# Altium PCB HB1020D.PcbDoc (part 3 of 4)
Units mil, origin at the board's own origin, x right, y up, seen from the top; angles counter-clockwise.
Board outline 4729.44 x 3075.9 mil, 2 copper layers (Top Layer, Bottom Layer); 113 components, 129 nets, 454 pads, 503 vias.
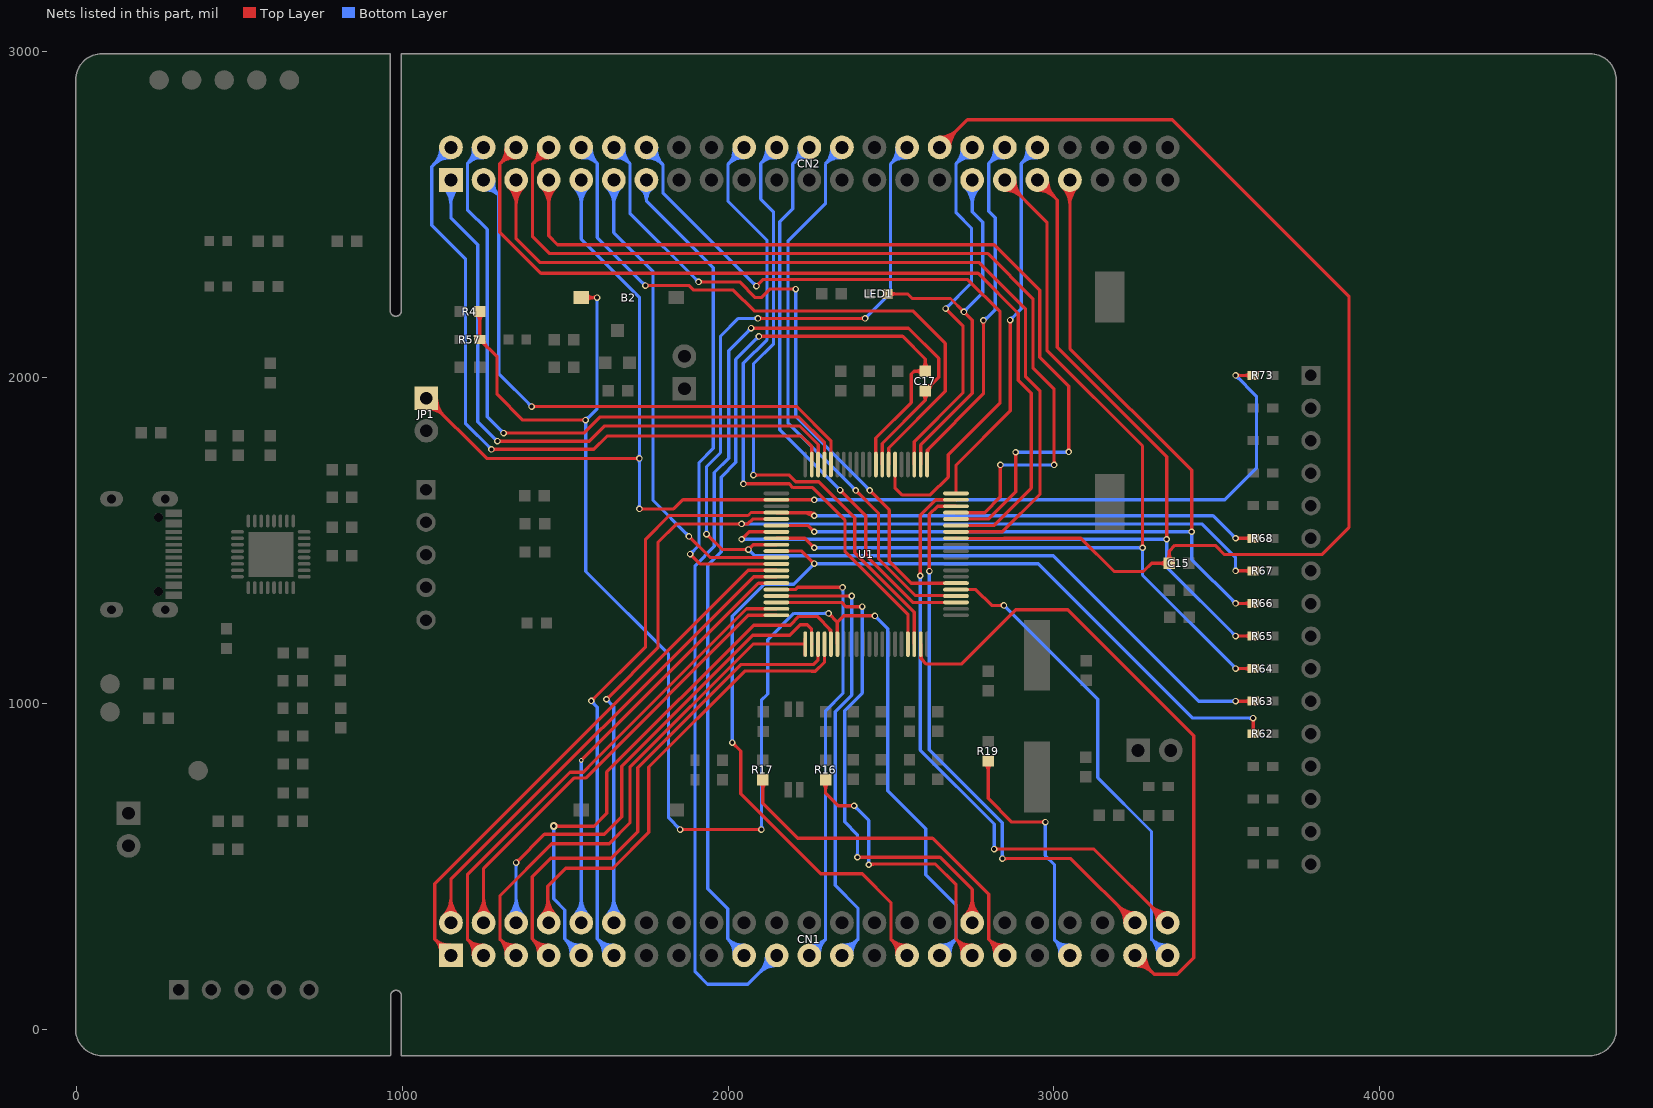
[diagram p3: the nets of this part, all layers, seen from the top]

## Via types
v1: diameter 20, hole 12, Top Layer to Bottom Layer, tented both sides, 475 vias
v2: diameter 23.62, hole 11.81, Top Layer to Bottom Layer, tented both sides, 20 vias
v3: diameter 122.05, hole 122.05, Top Layer to Bottom Layer, tented both sides, 4 vias
v4: diameter 39.37, hole 23.62, Top Layer to Bottom Layer, tented both sides, 2 vias
v5: diameter 30, hole 20, Top Layer to Bottom Layer, tented both sides, 1 vias
v6: diameter 15, hole 8, Top Layer to Bottom Layer, tented both sides, 1 vias

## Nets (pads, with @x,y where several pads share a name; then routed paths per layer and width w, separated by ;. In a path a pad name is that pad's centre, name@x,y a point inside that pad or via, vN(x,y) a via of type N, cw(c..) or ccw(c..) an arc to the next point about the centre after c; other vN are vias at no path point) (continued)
PB2: C15.1 CN2.32 U1.33 | length 3871
  Top Layer w10: CN2.32@2649.61,2706.79 2734.82,2792 3364,2792 3906,2250 3906,1540 3823,1457 3524,1457 3496,1485 3372,1485 3354.29,1467.29 C15.1@3354.29,1430.11 3300.11,1430.11 3275,1405 3185,1405 3083,1507 2847.46,1507 2847.07,1506.61 2700.24,1506.61 U1.33@2699.86,1507 ; CN2.32@2649.61,2728.21 ccw(c2649.61,2779.91) 2686.17,2743.35 ccw(c2722.73,2706.79) CN2.32@2671.02,2706.79 ; CN2.32@2649.61,2738.21 ccw(c2649.61,2814.05) 2703.24,2760.42 ccw(c2756.87,2706.79) CN2.32@2681.02,2706.79 ; C15.1@3345.45,1421.27 ccw(c3324.11,1399.93) 3324.11,1430.11 ccw(c3324.11,1460.28) 3345.45,1438.94 ccw(c3324.11,1460.28) 3354.29,1460.28 ccw(c3384.46,1460.28) C15.1@3363.13,1438.94
PB3: CN2.39 R66.1 U1.66 | length 3213.4
  Top Layer w10: U1.66@2148.68,1546.37 2245.31,1546.37 v1(2264.63,1527.06) ; v1@2259.63,1527.06 ccw(c2247.56,1527.06) 2256.09,1535.59 ccw(c2264.63,1544.13) v1@2264.63,1532.06 ; CN2.39@3027.39,2584.57 cw(c2973.76,2530.94) 3049.61,2530.94 cw(c3125.45,2530.94) CN2.39@3071.82,2584.57 ; CN2.39@3034.46,2591.64 cw(c2997.9,2555.08) 3049.61,2555.08 cw(c3101.31,2555.08) CN2.39@3064.75,2591.64 ; CN2.39@3049.61,2606.79 3049.61,2089.39 3423.34,1715.66 v1(3423.34,1527.06) ; v1@3419.8,1530.59 ccw(c3411.27,1539.13) 3423.34,1539.13 ccw(c3435.41,1539.13) v1@3426.87,1530.59 ; v1(3558,1307) R66.1@3612,1307 ; v1@3561.54,1303.46 cw(c3570.07,1294.93) 3570.07,1307 cw(c3570.07,1319.07) v1@3561.54,1310.54 ; R66.1@3602.07,1300.79 ccw(c3587.08,1285.8) 3587.08,1307 ccw(c3587.08,1328.2) R66.1@3602.07,1313.21
  Bottom Layer w10: v1(2264.63,1527.06) v1(3423.34,1527.06) 3423.34,1441.66 v1(3558,1307) ; v1@2268.17,1523.52 cw(c2276.7,1514.98) 2276.7,1527.06 cw(c2276.7,1539.13) v1@2268.17,1530.59 ; v1@3419.8,1530.59 cw(c3411.27,1539.13) 3411.27,1527.06 cw(c3411.27,1514.98) 3419.8,1523.52 cw(c3411.27,1514.98) 3423.34,1514.98 cw(c3435.41,1514.98) v1@3426.87,1523.52 ; v1@3553,1307 ccw(c3540.93,1307) 3549.46,1315.54 ccw(c3558,1324.07) v1@3558,1312
PB4: CN2.37 R65.1 U1.67 | length 3492.6
  Top Layer w10: v1(2042,1504) 2064.68,1526.69 U1.67@2148.68,1526.69 ; v1@2042,1509 ccw(c2042,1521.07) 2050.54,1512.54 ccw(c2059.07,1504) v1@2047,1504 ; CN2.37@2949.61,2575.37 cw(c2949.61,2499.52) 3003.24,2553.16 cw(c3056.87,2606.79) CN2.37@2981.02,2606.79 ; CN2.37@2949.61,2585.37 cw(c2949.61,2533.66) 2986.17,2570.23 cw(c3022.73,2606.79) CN2.37@2971.02,2606.79 ; CN2.37@2949.61,2606.79 3011,2545.39 3011,2093 3346.39,1757.61 v1(3346.39,1504) ; v1@3342.86,1507.54 ccw(c3334.32,1516.07) 3346.39,1516.07 ccw(c3358.47,1516.07) v1@3349.93,1507.54 ; v1(3558,1207) R65.1@3612,1207 ; v1@3561.54,1203.46 cw(c3570.07,1194.93) 3570.07,1207 cw(c3570.07,1219.07) v1@3561.54,1210.54 ; R65.1@3602.07,1200.79 ccw(c3587.08,1185.8) 3587.08,1207 ccw(c3587.08,1228.2) R65.1@3602.07,1213.21
  Bottom Layer w10: v1(2042,1504) v1(3346.39,1504) 3346.39,1418.61 v1(3558,1207) ; v1@2045.54,1500.46 cw(c2054.07,1491.93) 2054.07,1504 cw(c2054.07,1516.07) v1@2045.54,1507.54 ; v1@3342.86,1507.54 cw(c3334.32,1516.07) 3334.32,1504 cw(c3334.32,1491.93) 3342.86,1500.46 cw(c3334.32,1491.93) 3346.39,1491.93 cw(c3358.47,1491.93) v1@3349.93,1500.46 ; v1@3553,1207 ccw(c3540.93,1207) 3549.46,1215.54 ccw(c3558,1224.07) v1@3558,1212
PB5: CN2.35 R64.1 U1.68 | length 3341.8
  Top Layer w10: U1.68@2148.68,1507 2235.66,1507 v1(2264.63,1478.03) ; v1@2259.63,1478.03 ccw(c2247.56,1478.03) 2256.09,1486.56 ccw(c2264.63,1495.1) v1@2264.63,1483.03 ; CN2.35@2849.61,2575.37 cw(c2849.61,2499.52) 2903.24,2553.16 cw(c2956.87,2606.79) CN2.35@2881.02,2606.79 ; CN2.35@2849.61,2585.37 cw(c2849.61,2533.66) 2886.17,2570.23 cw(c2922.73,2606.79) CN2.35@2871.02,2606.79 ; CN2.35@2849.61,2606.79 2979,2477.39 2979,2084 3272.37,1790.63 v1(3272.37,1478.03) ; v1@3268.83,1481.56 ccw(c3260.3,1490.1) 3272.37,1490.1 ccw(c3284.44,1490.1) v1@3275.9,1481.56 ; v1(3558,1107) R64.1@3612,1107 ; v1@3561.54,1103.46 cw(c3570.07,1094.93) 3570.07,1107 cw(c3570.07,1119.07) v1@3561.54,1110.54 ; R64.1@3602.07,1100.79 ccw(c3587.08,1085.8) 3587.08,1107 ccw(c3587.08,1128.2) R64.1@3602.07,1113.21
  Bottom Layer w10: v1(2264.63,1478.03) v1(3272.37,1478.03) 3272.37,1394.11 v1@3558.48,1108 ; v1@2268.17,1474.49 cw(c2276.7,1465.96) 2276.7,1478.03 cw(c2276.7,1490.1) v1@2268.17,1481.56 ; v1@3268.83,1481.56 cw(c3260.3,1490.1) 3260.3,1478.03 cw(c3260.3,1465.96) 3268.83,1474.49 cw(c3260.3,1465.96) 3272.37,1465.96 cw(c3284.44,1465.96) v1@3275.9,1474.49 ; 3548.42,1118.06 cw(c3537.36,1107) v1@3553,1107
PB6: CN2.30 R63.1 U1.69 | length 4077.3
  Top Layer w10: v1@1934,1515 cw(c1934,1500.51) 1944.24,1510.76 ; v1(1934,1520) 1935,1520 1982.5,1472.5 v1(2062.5,1472.5) 2077.31,1487.31 U1.69@2148.68,1487.31 ; v1@1939,1520 ccw(c1948.66,1520) 1941.83,1513.17 ; v1@2058.96,1468.96 ccw(c2050.43,1460.43) 2050.43,1472.5 ccw(c2050.43,1484.57) v1@2058.96,1476.04 ; v1@2062.5,1477.5 ccw(c2062.5,1489.57) 2071.04,1481.04 ccw(c2079.57,1472.5) v1@2067.5,1472.5 ; v1(2092,2182) v1(2421,2182) ; v1@2095.54,2178.46 cw(c2104.07,2169.93) 2104.07,2182 cw(c2104.07,2194.07) v1@2095.54,2185.54 ; v1@2417.46,2178.46 ccw(c2408.93,2169.93) 2408.93,2182 ccw(c2408.93,2194.07) v1@2417.46,2185.54 ; v1(3558,1007) R63.1@3612,1007 ; v1@3561.54,1003.46 cw(c3570.07,994.93) 3570.07,1007 cw(c3570.07,1019.07) v1@3561.54,1010.54 ; R63.1@3602.07,1000.79 ccw(c3587.08,985.8) 3587.08,1007 ccw(c3587.08,1028.2) R63.1@3602.07,1013.21
  Bottom Layer w10: v1@1930.46,1523.54 ccw(c1921.93,1532.07) 1934,1532.07 ccw(c1946.07,1532.07) v1@1937.54,1523.54 ; v1(1934,1520) 1934,1727 1977,1770 1977,2127 2032,2182 v1(2092,2182) ; v1@2062.5,1467.5 cw(c2062.5,1455.43) 2071.04,1463.96 cw(c2079.57,1472.5) v1@2067.5,1472.5 ; v1(2062.5,1472.5) 2082,1453 2999,1453 3445,1007 v1(3558,1007) ; v1@2088.46,2178.46 ccw(c2079.93,2169.93) 2079.93,2182 ccw(c2079.93,2194.07) v1@2088.46,2185.54 ; v1(2421,2182) 2499.02,2260.02 2499.02,2656.2 ; v1@2421,2187 ccw(c2421,2199.07) 2429.54,2190.54 ccw(c2438.07,2182) v1@2426,2182 ; CN2.30@2518.22,2705.46 cw(c2452.55,2702.68) 2499.03,2656.21 ; CN2.30@2528.21,2705.88 cw(c2483.44,2703.99) 2515.13,2672.31 cw(c2546.81,2640.63) CN2.30@2548.7,2685.39 ; CN2.30@2548.28,2675.4 ccw(c2545.5,2609.73) 2499.03,2656.21 ; CN2.30@2549.61,2706.79 2499.02,2656.2 ; v1@3554.46,1003.46 ccw(c3545.93,994.93) 3545.93,1007 ccw(c3545.93,1019.07) v1@3554.46,1010.54
PB7: CN1.29 R62.1 U1.70 | length 3723.2
  Top Layer w10: v1@2013,875 cw(c2013,862.93) 2021.54,871.46 cw(c2030.07,880) v1@2018,880 ; v1(2013,880) 2039,854 2039,723 2285,477 2412,477 2500,389 2500,276.39 ; U1.70@2148.68,1467.63 2226,1467.63 v1(2264.63,1429) ; v1@2259.63,1429 ccw(c2247.56,1429) 2256.09,1437.54 ccw(c2264.63,1446.07) v1@2264.63,1434 ; CN1.29@2518.24,228.57 ccw(c2455.73,232.12) 2500,276.39 ; CN1.29@2528.22,228 ccw(c2485.61,230.42) 2515.79,260.6 ccw(c2545.97,290.78) CN1.29@2548.39,248.17 ; CN1.29@2547.82,258.15 cw(c2544.27,320.66) 2500,276.39 ; CN1.29@2549.61,226.79 2500,276.39 ; R62.1@3605.79,913.21 ccw(c3590.8,928.2) 3612,928.2 ccw(c3633.2,928.2) R62.1@3618.21,913.21 ; v1@3608.46,951.46 cw(c3599.93,942.93) 3612,942.93 cw(c3624.07,942.93) v1@3615.54,951.46 ; R62.1@3612,907 v1(3612,955)
  Bottom Layer w10: v1@2009.46,883.54 ccw(c2000.93,892.07) 2013,892.07 ccw(c2025.07,892.07) v1@2016.54,883.54 ; v1(2013,880) 2013,1268 2111.09,1366.09 2201.72,1366.09 v1(2264.63,1429) 2952,1429 3426,955 v1(3612,955) ; v1@2259.63,1429 cw(c2247.56,1429) 2256.09,1420.46 cw(c2264.63,1411.93) v1@2264.63,1424 ; v1@2268.17,1425.46 cw(c2276.7,1416.93) 2276.7,1429 cw(c2276.7,1441.07) v1@2268.17,1432.54 ; v1@3608.46,951.46 ccw(c3599.93,942.93) 3599.93,955 ccw(c3599.93,967.07) v1@3608.46,958.54
PB8: CN2.11 U1.71 | length 1723.1
  Top Layer w10: v1@1880,1508 cw(c1880,1495.93) 1888.54,1504.46 cw(c1897.07,1513) v1@1885,1513 ; v1(1880,1513) 1945.05,1447.94 U1.71@2148.68,1447.94
  Bottom Layer w10: CN2.11@1627.39,2584.57 cw(c1573.76,2530.94) 1649.61,2530.94 cw(c1725.45,2530.94) CN2.11@1671.82,2584.57 ; CN2.11@1634.46,2591.64 cw(c1597.9,2555.08) 1649.61,2555.08 cw(c1701.31,2555.08) CN2.11@1664.75,2591.64 ; CN2.11@1649.61,2606.79 1649.61,2445.39 1770,2325 1770,1623 v1(1880,1513) ; v1@1875,1513 ccw(c1862.93,1513) 1871.46,1521.54 ccw(c1880,1530.07) v1@1880,1518
PB9: CN2.13 U1.72 | length 1728.3
  Top Layer w10: v1@1883.73,1453.27 cw(c1883.73,1441.2) 1892.27,1449.73 cw(c1900.8,1458.27) v1@1888.73,1458.27 ; v1(1883.73,1458.27) 1913.74,1428.26 U1.72@2148.68,1428.26 U1.72@2148.29,1428.65
  Bottom Layer w10: CN2.13@1730.58,2581.79 cw(c1701.36,2543.4) 1749.61,2543.4 ; CN2.13@1736.64,2589.75 cw(c1716.72,2563.57) 1749.61,2563.57 cw(c1782.49,2563.57) CN2.13@1762.58,2589.75 ; CN2.13@1749.61,2606.79 1749.61,2543.39 ; CN2.13@1768.63,2581.79 ccw(c1797.85,2543.4) 1749.61,2543.4 ; v1(1883.73,1458.27) 1911,1485.54 1911,1739 1955,1783 1955,2338 1749.61,2543.39 ; v1@1883.73,1463.27 ccw(c1883.73,1475.34) 1892.27,1466.8 ccw(c1900.8,1458.27) v1@1888.73,1458.27
PB10: CN1.44 U1.38 | length 2006.9
  Top Layer w10: v1@2614.46,1409.54 ccw(c2605.93,1418.07) 2618,1418.07 ccw(c2630.07,1418.07) v1@2621.54,1409.54 ; v1(2618,1406) 2618,1580.08 2643.34,1605.43 U1.38@2699.86,1605.43 ; v1(2842,523.73) 3052.66,523.73 CN1.44@3249.61,326.79 ; v1@2845.54,520.2 cw(c2854.07,511.66) 2854.07,523.73 cw(c2854.07,535.8) v1@2845.54,527.27 ; CN1.44@3218.19,326.79 ccw(c3142.34,326.79) 3195.97,380.42 ccw(c3249.61,434.05) CN1.44@3249.61,358.21 ; CN1.44@3228.19,326.79 ccw(c3176.48,326.79) 3213.04,363.35 ccw(c3249.61,399.91) CN1.44@3249.61,348.21
  Bottom Layer w10: v1@2614.46,1402.46 cw(c2605.93,1393.93) 2618,1393.93 cw(c2630.07,1393.93) v1@2621.54,1402.46 ; v1(2618,1406) 2618,858 2842,634 v1(2842,523.73) ; v1@2838.46,527.27 ccw(c2829.93,535.8) 2842,535.8 ccw(c2854.07,535.8) v1@2845.54,527.27
PB11: CN1.46 U1.39 | length 2151
  Top Layer w10: v1@2586.46,1395.54 ccw(c2577.93,1404.07) 2590,1404.07 ccw(c2602.07,1404.07) v1@2593.54,1395.54 ; v1(2590,1392) 2590,1577.54 2637.96,1625.5 2699.47,1625.5 U1.39@2699.86,1625.11 ; v1(2817,553) 3123.39,553 CN1.46@3349.61,326.79 ; v1@2820.54,549.46 cw(c2829.07,540.93) 2829.07,553 cw(c2829.07,565.07) v1@2820.54,556.54 ; CN1.46@3318.19,326.79 ccw(c3242.34,326.79) 3295.97,380.42 ccw(c3349.61,434.05) CN1.46@3349.61,358.21 ; CN1.46@3328.19,326.79 ccw(c3276.48,326.79) 3313.04,363.35 ccw(c3349.61,399.91) CN1.46@3349.61,348.21
  Bottom Layer w10: v1@2586.46,1388.46 cw(c2577.93,1379.93) 2590,1379.93 cw(c2602.07,1379.93) v1@2593.54,1388.46 ; v1(2590,1392) 2590,857 2817,630 v1(2817,553) ; v1@2813.46,556.54 ccw(c2804.93,565.07) 2817,565.07 ccw(c2829.07,565.07) v1@2820.54,556.54
PB12: CN2.38 U1.40 | length 1379.6
  Top Layer w10: U1.40@2699.86,1644.8 2699.86,1731.86 2866,1898 v1(2866,2177) ; v1@2862.46,2173.46 cw(c2853.93,2164.93) 2866,2164.93 cw(c2878.07,2164.93) v1@2869.54,2173.46
  Bottom Layer w10: v1(2866,2177) 2900.19,2211.19 2900.19,2657.37 ; v1@2866,2182 ccw(c2866,2194.07) 2874.54,2185.54 ccw(c2883.07,2177) v1@2871,2177 ; CN2.38@2918.24,2704.92 cw(c2856.34,2701.22) 2900.19,2657.37 ; CN2.38@2928.23,2705.51 cw(c2886.03,2702.99) 2915.92,2673.1 cw(c2945.81,2643.21) CN2.38@2948.33,2685.41 ; CN2.38@2947.74,2675.43 ccw(c2944.04,2613.52) 2900.19,2657.37 ; CN2.38@2949.61,2706.79 2900.19,2657.37
PB13: CN2.36 U1.41 | length 1324.7
  Top Layer w10: U1.41@2611.28,1733.38 2611.28,1777.28 2784,1950 v1(2784,2176) ; U1.41@2612.18,1766.84 cw(c2639.56,1766.84) 2620.2,1786.2 ; v1@2780.46,2172.46 cw(c2771.93,2163.93) 2784,2163.93 cw(c2796.07,2163.93) v1@2787.54,2172.46
  Bottom Layer w10: v1(2784,2176) 2788,2176 2820,2208 2820,2490.65 2800.19,2510.46 2800.19,2657.37 ; v1@2784,2181 ccw(c2784,2202.73) 2799.36,2187.36 ; CN2.36@2818.24,2704.92 cw(c2756.34,2701.22) 2800.19,2657.37 ; CN2.36@2828.23,2705.51 cw(c2786.03,2702.99) 2815.92,2673.1 cw(c2845.81,2643.21) CN2.36@2848.33,2685.41 ; CN2.36@2847.74,2675.43 ccw(c2844.04,2613.52) 2800.19,2657.37 ; CN2.36@2849.61,2706.79 2800.19,2657.37
PB14: CN2.33 LED1.2 U1.42 | length 1539.3
  Top Layer w10: LED1.2@2490,2257 2551.01,2257 2565.01,2243 2683,2243 v1(2724,2202) 2750,2176 2750,1952 2591.59,1793.59 U1.42@2591.59,1733.38 ; LED1.2@2497.07,2249.93 cw(c2514.14,2232.86) 2514.14,2257 cw(c2514.14,2281.14) LED1.2@2497.07,2264.07 ; v1@2719,2202 ccw(c2706.93,2202) 2715.46,2210.54 ccw(c2724,2219.07) v1@2724,2207 ; v1@2724,2197 cw(c2724,2184.93) 2732.54,2193.46 cw(c2741.07,2202) v1@2729,2202
  Bottom Layer w10: v1(2724,2202) 2782.19,2260.19 2782.19,2476.81 2749.61,2509.39 CN2.33@2749.61,2606.79 ; v1@2724,2207 ccw(c2724,2219.07) 2732.54,2210.54 ccw(c2741.07,2202) v1@2729,2202 ; CN2.33@2727.39,2584.57 cw(c2673.76,2530.94) 2749.61,2530.94 cw(c2825.45,2530.94) CN2.33@2771.82,2584.57 ; CN2.33@2734.46,2591.64 cw(c2697.9,2555.08) 2749.61,2555.08 cw(c2801.31,2555.08) CN2.33@2764.75,2591.64
PB15: CN2.34 U1.43 | length 1344.3
  Top Layer w10: U1.43@2571.91,1733.38 2571.91,1803.91 2721,1953 2721,2159 v1(2668,2212) ; v1@2668,2207 cw(c2668,2194.93) 2676.54,2203.46 cw(c2685.07,2212) v1@2673,2212
  Bottom Layer w10: v1(2668,2212) 2747.5,2291.5 2747.5,2459.32 2700.19,2506.63 2700.19,2657.37 ; v1@2668,2217 ccw(c2668,2229.07) 2676.54,2220.54 ccw(c2685.07,2212) v1@2673,2212 ; CN2.34@2718.24,2704.92 cw(c2656.34,2701.22) 2700.19,2657.37 ; CN2.34@2728.23,2705.51 cw(c2686.03,2702.99) 2715.92,2673.1 cw(c2745.81,2643.21) CN2.34@2748.33,2685.41 ; CN2.34@2747.74,2675.43 ccw(c2744.04,2613.52) 2700.19,2657.37 ; CN2.34@2749.61,2706.79 2700.19,2657.37
PC0: CN2.20 U1.17 | length 2167
  Top Layer w10: v1(2047,1674) 2188.05,1674 2199.35,1662.7 2259.57,1662.7 2359,1563.27 2359,1467.54 2552.22,1274.32 U1.17@2552.22,1182.2 ; v1@2050.54,1670.46 cw(c2059.07,1661.93) 2059.07,1674 cw(c2059.07,1686.07) v1@2050.54,1677.54 ; U1.17@2552.55,1160.93 U1.17@2553.1,1161.48
  Bottom Layer w10: 2016.27,2671.27 ccw(c1986.81,2700.74) CN2.20@2028.29,2704.73 ; 2017.82,2672.82 cw(c2048.16,2642.49) CN2.20@2049.12,2685.38 ; CN2.20@2018.33,2703.78 cw(c1959.46,2698.11) 2001.28,2656.28 cw(c2047.43,2610.14) CN2.20@2048.9,2675.38 ; v1@2043.46,1677.54 ccw(c2034.93,1686.07) 2047,1686.07 ccw(c2059.07,1686.07) v1@2050.54,1677.54 ; v1(2047,1674) 2047,2044 2120,2117 2120,2421 2000.19,2540.81 2000.19,2655.19 2049.61,2704.61 CN2.20@2049.61,2706.79
PC1: CN2.22 U1.18 | length 2111.4
  Top Layer w10: v1(2078,1701) 2188,1701 2208.3,1680.7 2278.3,1680.7 2389,1570 2389,1463 2571.91,1280.09 U1.18@2571.91,1182.2 ; v1@2081.54,1697.46 cw(c2090.07,1688.93) 2090.07,1701 cw(c2090.07,1713.07) v1@2081.54,1704.54
  Bottom Layer w10: v1@2074.46,1704.54 ccw(c2065.93,1713.07) 2078,1713.07 ccw(c2090.07,1713.07) v1@2081.54,1704.54 ; v1(2078,1701) 2078,2042 2140,2104 2140,2508.44 2100.19,2548.25 2100.19,2657.37 ; CN2.22@2118.24,2704.92 cw(c2056.34,2701.22) 2100.19,2657.37 ; CN2.22@2128.23,2705.51 cw(c2086.03,2702.99) 2115.92,2673.1 cw(c2145.81,2643.21) CN2.22@2148.33,2685.41 ; CN2.22@2147.74,2675.43 ccw(c2144.04,2613.52) 2100.19,2657.37 ; CN2.22@2149.61,2706.79 2100.19,2657.37
PC2: CN1.43 U1.19 | length 2247.5
  Top Layer w10: U1.19@2591.59,1182.2 2591.59,1138.41 2609,1121 2716,1121 2883,1288 3043,1288 3430,901 3430,219.73 3378.79,168.52 3307.87,168.52 CN1.43@3249.61,226.79 ; U1.19@2592.5,1148.73 ccw(c2619.6,1148.73) 2600.43,1129.57 ; CN1.43@3249.61,195.37 cw(c3249.61,119.52) 3303.24,173.16 cw(c3356.87,226.79) CN1.43@3281.02,226.79 ; CN1.43@3249.61,205.37 cw(c3249.61,153.66) 3286.17,190.23 cw(c3322.73,226.79) CN1.43@3271.02,226.79
PC3: CN2.24 U1.23 | length 1956.7
  Top Layer w10: v1@2344,1650 cw(c2344,1637.93) 2352.54,1646.46 cw(c2361.07,1655) v1@2349,1655 ; v1(2344,1655) 2423,1576 2423,1454.48 2567.33,1310.15 U1.23@2699.86,1310.15
  Bottom Layer w10: CN2.24@2218.22,2705.46 cw(c2152.55,2702.68) 2199.03,2656.21 ; CN2.24@2228.21,2705.88 cw(c2183.44,2703.99) 2215.13,2672.31 cw(c2246.81,2640.63) CN2.24@2248.7,2685.39 ; CN2.24@2248.28,2675.4 ccw(c2245.5,2609.73) 2199.03,2656.21 ; CN2.24@2249.61,2706.79 2199.02,2656.2 ; v1@2339,1655 ccw(c2326.93,1655) 2335.46,1663.54 ccw(c2344,1672.07) v1@2344,1660 ; v1(2344,1655) 2159,1840 2159,2478.31 2199.02,2518.33 2199.02,2656.2
PC4: CN2.26 U1.24 | length 1959.2
  Top Layer w10: v1@2392,1649 cw(c2392,1636.93) 2400.54,1645.46 cw(c2409.07,1654) v1@2397,1654 ; v1(2392,1654) 2462,1584 2462,1443.54 2574.02,1331.52 2698.17,1331.52 U1.24@2699.86,1329.83 ; 2660.14,1331.52 cw(c2660.14,1323.58) U1.24@2665.75,1329.19
  Bottom Layer w10: 2299,2627.28 2299,2656.18 ; 2299.02,2627.26 2299.02,2533.51 2184,2418.48 2184,1862 v1(2392,1654) ; CN2.26@2318.22,2705.47 cw(c2252.48,2702.71) 2299,2656.18 ; CN2.26@2328.21,2705.89 cw(c2283.39,2704.01) 2315.11,2672.29 cw(c2346.83,2640.57) CN2.26@2348.71,2685.39 ; CN2.26@2348.29,2675.4 ccw(c2345.53,2609.66) 2299,2656.18 ; CN2.26@2349.61,2706.79 2299,2656.18 ; v1@2387,1654 ccw(c2374.93,1654) 2383.46,1662.54 ccw(c2392,1671.07) v1@2392,1659
PC5: CN1.45 U1.25 | length 1664.9
  Top Layer w10: U1.25@2699.86,1349.52 2760.48,1349.52 2809,1301 v1(2847,1301) ; v1@2843.46,1297.46 ccw(c2834.93,1288.93) 2834.93,1301 ccw(c2834.93,1313.07) v1@2843.46,1304.54
  Bottom Layer w10: v1@2847,1296 cw(c2847,1283.93) 2855.54,1292.46 cw(c2864.07,1301) v1@2852,1301 ; v1(2847,1301) 3134.61,1013.39 3134.61,772.39 3300,607 3300,276.39 ; CN1.45@3318.24,228.57 ccw(c3255.73,232.12) 3300,276.39 ; CN1.45@3328.22,228 ccw(c3285.61,230.42) 3315.79,260.6 ccw(c3345.97,290.78) CN1.45@3348.39,248.17 ; CN1.45@3347.82,258.15 cw(c3344.27,320.66) 3300,276.39 ; CN1.45@3349.61,226.79 3300,276.39
PC6: CN2.12 U1.26 | length 2327.2
  Top Layer w10: v1(1909.5,2294) 2036,2294 2084,2246 2102,2246 2128,2272 v1(2208,2272) ; v1@1913.04,2290.46 cw(c1921.57,2281.93) 1921.57,2294 cw(c1921.57,2306.07) v1@1913.04,2297.54 ; v1@2204.46,2268.46 ccw(c2195.93,2259.93) 2195.93,2272 ccw(c2195.93,2284.07) v1@2204.46,2275.54 ; v1@2435,1649 cw(c2435,1636.93) 2443.54,1645.46 cw(c2452.07,1654) v1@2440,1654 ; v1(2435,1654) 2495,1594 2495,1436 2562,1369 2699.65,1369 U1.26@2699.86,1369.2
  Bottom Layer w10: CN2.12@1649.61,2706.79 1699.02,2657.37 ; CN2.12@1650.88,2685.41 cw(c1653.4,2643.21) 1683.29,2673.1 cw(c1713.19,2702.99) CN2.12@1670.99,2705.51 ; CN2.12@1651.48,2675.43 cw(c1655.17,2613.52) 1699.02,2657.37 ; CN2.12@1680.97,2704.92 ccw(c1742.87,2701.22) 1699.02,2657.37 ; v1@1904.5,2294 ccw(c1892.43,2294) 1900.96,2302.54 ccw(c1909.5,2311.07) v1@1909.5,2299 ; v1(1909.5,2294) 1699.02,2504.48 1699.02,2657.37 ; v1@2204.46,2268.46 cw(c2195.93,2259.93) 2208,2259.93 cw(c2220.07,2259.93) v1@2211.54,2268.46 ; v1(2208,2272) 2208,1881 v1(2435,1654) ; v1@2430,1654 ccw(c2417.93,1654) 2426.46,1662.54 ccw(c2435,1671.07) v1@2435,1659
PC7: CN2.14 U1.46 | length 2423.8
  Top Layer w10: v1(2087,2281) 2107,2301 2736,2301 2835,2202 2835,1923 2676,1764 2676,1695 2621,1640 2534,1640 2512.47,1661.54 2512.47,1732.99 U1.46@2512.85,1733.38 ; v1@2087,2286 ccw(c2087,2298.07) 2095.54,2289.54 ccw(c2104.07,2281) v1@2092,2281
  Bottom Layer w10: CN2.14@1749.66,2685.37 cw(c1749.76,2639.81) 1781.97,2672.03 ; CN2.14@1749.61,2706.79 1749.61,2704.39 1800.19,2653.81 1800.19,2567.81 v1(2087,2281) ; CN2.14@1749.68,2675.37 cw(c1749.84,2605.86) 1798.99,2655.01 cw(c1843.12,2699.14) CN2.14@1780.92,2704.23 ; CN2.14@1770.95,2705.04 ccw(c1814.87,2701.45) 1783.71,2670.29 ; v1@2082,2281 ccw(c2069.93,2281) 2078.46,2289.54 ccw(c2087,2298.07) v1@2087,2286
PC8: CN2.10 U1.47 | length 2157.7
  Top Layer w10: v1(1746.23,2282.77) 1881.23,2282.77 1895,2269 2016,2269 2080,2205 2567,2205 2667,2105 2667,1958 2493.17,1784.17 U1.47@2493.17,1733.38 ; v1@1749.76,2279.24 cw(c1758.3,2270.7) 1758.3,2282.77 cw(c1758.3,2294.84) v1@1749.76,2286.31
  Bottom Layer w10: CN2.10@1549.61,2706.79 1599.02,2657.37 ; CN2.10@1550.88,2685.41 cw(c1553.4,2643.21) 1583.29,2673.1 cw(c1613.19,2702.99) CN2.10@1570.99,2705.51 ; CN2.10@1551.48,2675.43 cw(c1555.17,2613.52) 1599.02,2657.37 ; CN2.10@1580.97,2704.92 ccw(c1642.87,2701.22) 1599.02,2657.37 ; v1@1741.23,2282.77 ccw(c1729.16,2282.77) 1737.69,2291.31 ccw(c1746.23,2299.84) v1@1746.23,2287.77 ; v1(1746.23,2282.77) 1599.02,2429.98 1599.02,2657.37
PC9: CN2.9 JP1.1 R73.1 U1.62 | length 4730.6
  Top Layer w10: JP1.1@1074,1905.58 cw(c1074,1829.73) 1127.63,1883.37 cw(c1181.26,1937) JP1.1@1105.42,1937 ; JP1.1@1074,1915.58 cw(c1074,1863.88) 1110.56,1900.44 cw(c1147.12,1937) JP1.1@1095.42,1937 ; JP1.1@1074,1937 1259,1752 v1(1728,1752) ; v1@1724.46,1748.46 ccw(c1715.93,1739.93) 1715.93,1752 ccw(c1715.93,1764.07) v1@1724.46,1755.54 ; v1(1728,1597) 1833,1597 1861.5,1625.5 2148.29,1625.5 U1.62@2148.68,1625.11 v1(2264.63,1625.11) ; v1@1731.54,1593.46 cw(c1740.07,1584.93) 1740.07,1597 cw(c1740.07,1609.07) v1@1731.54,1600.54 ; v1@2261.09,1621.57 ccw(c2252.56,1613.04) 2252.56,1625.11 ccw(c2252.56,1637.18) v1@2261.09,1628.65 ; v1(3558,2007) R73.1@3612,2007 ; v1@3561.54,2003.46 cw(c3570.07,1994.93) 3570.07,2007 cw(c3570.07,2019.07) v1@3561.54,2010.54 ; R73.1@3602.07,2000.79 ccw(c3587.08,1985.8) 3587.08,2007 ccw(c3587.08,2028.2) R73.1@3602.07,2013.21
  Bottom Layer w10: CN2.9@1527.39,2584.57 cw(c1473.76,2530.94) 1549.61,2530.94 cw(c1625.45,2530.94) CN2.9@1571.82,2584.57 ; CN2.9@1534.46,2591.64 cw(c1497.9,2555.08) 1549.61,2555.08 cw(c1601.31,2555.08) CN2.9@1564.75,2591.64 ; CN2.9@1549.61,2606.79 1549.61,2425.39 1728,2247 v1(1728,1597) ; v1@1724.46,1600.54 ccw(c1715.93,1609.07) 1728,1609.07 ccw(c1740.07,1609.07) v1@1731.54,1600.54 ; v1@1724.46,1748.46 cw(c1715.93,1739.93) 1728,1739.93 cw(c1740.07,1739.93) v1@1731.54,1748.46 ; v1@1724.46,1755.54 ccw(c1715.93,1764.07) 1728,1764.07 ccw(c1740.07,1764.07) v1@1731.54,1755.54 ; v1(2264.63,1625.11) 3525.11,1625.11 3622,1722 3622,1943 v1(3558,2007) ; v1@2268.17,1621.57 cw(c2276.7,1613.04) 2276.7,1625.11 cw(c2276.7,1637.18) v1@2268.17,1628.65 ; v1@3558,2002 cw(c3558,1989.93) 3566.54,1998.46 cw(c3575.07,2007) v1@3563,2007
PC10: CN1.11 R68.1 U1.64 | length 3670
  Top Layer w10: v1(1580.32,1007.68) 1581.01,1007.68 1747,1173.67 1747,1504 1820,1577 2061.54,1577 2070.67,1586.13 2148.29,1586.13 U1.64@2148.68,1585.74 2254.97,1585.74 v1(2264.63,1576.08) ; v1@1580.32,1012.68 ccw(c1580.32,1026.42) 1590.03,1016.7 ; v1@1585.32,1007.68 cw(c1595.73,1007.68) 1588.37,1015.04 ; 2229.24,1585.74 cw(c2229.24,1540.69) v1@2261.09,1572.55 ; 2253.38,1585.74 cw(c2253.38,1564.84) v1@2268.17,1579.62 ; v1(3558,1507) R68.1@3612,1507 ; v1@3561.54,1503.46 cw(c3570.07,1494.93) 3570.07,1507 cw(c3570.07,1519.07) v1@3561.54,1510.54 ; R68.1@3602.07,1500.79 ccw(c3587.08,1485.8) 3587.08,1507 ccw(c3587.08,1528.2) R68.1@3602.07,1513.21
  Bottom Layer w10: v1@1580.32,1002.68 cw(c1580.32,990.61) 1588.85,999.15 cw(c1597.39,1007.68) v1@1585.32,1007.68 ; v1(1580.32,1007.68) 1599.02,988.98 1599.02,277.37 ; CN1.11@1618.22,228.12 ccw(c1552.56,230.9) 1599.03,277.37 ; CN1.11@1628.21,227.69 ccw(c1583.45,229.59) 1615.13,261.27 ccw(c1646.81,292.95) CN1.11@1648.7,248.19 ; CN1.11@1648.28,258.18 cw(c1645.5,323.84) 1599.03,277.37 ; CN1.11@1649.61,226.79 1599.02,277.37 ; v1(2264.63,1576.08) 3488.92,1576.08 v1(3558,1507) ; v1@2268.17,1572.55 cw(c2276.7,1564.01) 2276.7,1576.08 cw(c2276.7,1588.15) v1@2268.17,1579.62 ; v1@3553,1507 ccw(c3540.93,1507) 3549.46,1515.54 ccw(c3558,1524.07) v1@3558,1512
PC11: CN1.12 R67.1 U1.65 | length 3655.4
  Top Layer w10: v1(1627,1013) 1627.61,1013 1785,1170.39 1785,1494 1842,1551 v1(2042,1551) 2061,1551 2076.05,1566.06 U1.65@2148.68,1566.06 ; v1@1627,1018 ccw(c1627,1031.53) 1636.57,1021.96 ; v1@1632,1013 cw(c1642.61,1013) 1635.11,1020.5 ; v1@2038.46,1547.46 ccw(c2029.93,1538.93) 2029.93,1551 ccw(c2029.93,1563.07) v1@2038.46,1554.54 ; v1@2045.54,1547.46 cw(c2054.07,1538.93) 2054.07,1551 cw(c2054.07,1563.07) v1@2045.54,1554.54 ; v1(3558,1407) R67.1@3612,1407 ; v1@3561.54,1403.46 cw(c3570.07,1394.93) 3570.07,1407 cw(c3570.07,1419.07) v1@3561.54,1410.54 ; R67.1@3602.07,1400.79 ccw(c3587.08,1385.8) 3587.08,1407 ccw(c3587.08,1428.2) R67.1@3602.07,1413.21
  Bottom Layer w10: v1@1627,1008 cw(c1627,995.93) 1635.54,1004.46 cw(c1644.07,1013) v1@1632,1013 ; v1(1627,1013) 1649.61,990.39 CN1.12@1649.61,326.79 ; CN1.12@1627.39,349 ccw(c1573.76,402.64) 1649.61,402.64 ccw(c1725.45,402.64) CN1.12@1671.82,349 ; CN1.12@1634.46,341.93 ccw(c1597.9,378.49) 1649.61,378.49 ccw(c1701.31,378.49) CN1.12@1664.75,341.93 ; v1(2042,1551) 3454,1551 3558,1447 v1(3558,1407) ; v1@2045.54,1547.46 cw(c2054.07,1538.93) 2054.07,1551 cw(c2054.07,1563.07) v1@2045.54,1554.54 ; v1@3554.46,1410.54 ccw(c3545.93,1419.07) 3558,1419.07 ccw(c3570.07,1419.07) v1@3561.54,1410.54
PC12: CN1.9 U1.5 | length 1939.7
  Top Layer w10: v2(1465,624) 1466,623 1588.66,623 1628,662.34 1628,789.7 2078.61,1240.31 2190.79,1240.31 2217.61,1267.13 2274,1267.13 2316,1225.13 U1.5@2316,1182.2 ; v2@1469.82,619.18 cw(c1479.03,609.97) 1479.03,623 ; v2@1469.82,628.82 ccw(c1483.86,642.86) 1483.86,623 ; 2307.76,1233.36 cw(c2290.06,1215.66) U1.5@2315.09,1215.66
  Bottom Layer w10: v2@1460.18,619.18 cw(c1448.56,607.56) 1465,607.56 cw(c1481.44,607.56) v2@1469.82,619.18 ; v2(1465,624) 1465,400 1499.02,365.98 1499.02,277.37 ; CN1.9@1518.22,228.12 ccw(c1452.56,230.9) 1499.03,277.37 ; CN1.9@1528.21,227.69 ccw(c1483.45,229.59) 1515.13,261.27 ccw(c1546.81,292.95) CN1.9@1548.7,248.19 ; CN1.9@1548.28,258.18 cw(c1545.5,323.84) 1499.03,277.37 ; CN1.9@1549.61,226.79 1499.02,277.37
PC13: B2.2 CN1.31 R4.1 R57.1 U1.6 | length 5450.5
  Top Layer w10: R4.1@1229.16,2194.16 cw(c1207.82,2172.82) 1238,2172.82 cw(c1268.18,2172.82) R4.1@1246.84,2194.16 ; R57.1@1231.79,2123.21 ccw(c1216.8,2138.2) 1238,2138.2 ccw(c1259.2,2138.2) R57.1@1244.21,2123.21 ; R4.1@1238,2203 R57.1@1238,2117 1291,2064 1291,1949 1370,1870 v1(1563,1870) ; R57.1@1241.72,2108.22 cw(c1241.72,2096.01) R57.1@1250.36,2104.64 ; R57.1@1250.5,2117 ccw(c1280.68,2117) 1259.34,2095.66 ; B2.2@1549.61,2246 v1(1598,2246) ; v1@1559.46,1866.46 ccw(c1550.93,1857.93) 1550.93,1870 ccw(c1550.93,1882.07) v1@1559.46,1873.54 ; B2.2@1563.93,2235.62 cw(c1589,2210.55) 1589,2246 cw(c1589,2281.45) B2.2@1563.93,2256.38 ; v1@1594.46,2242.46 ccw(c1585.93,2233.93) 1585.93,2246 ccw(c1585.93,2258.07) v1@1594.46,2249.54 ; v1(1853,613) v1(2102.64,613) ; v1@1856.54,609.46 cw(c1865.07,600.93) 1865.07,613 cw(c1865.07,625.07) v1@1856.54,616.54 ; v1@2099.11,609.46 ccw(c2090.57,600.93) 2090.57,613 ccw(c2090.57,625.07) v1@2099.11,616.54 ; v1@2309,1271.37 cw(c2309,1259.3) 2317.54,1267.83 cw(c2326.07,1276.37) v1@2314,1276.37 ; v1(2309,1276.37) 2335.68,1249.69 ; U1.6@2335.68,1182.2 2335.68,1249.69 ; v1@2447.46,1265.46 ccw(c2438.93,1256.93) 2438.93,1269 ccw(c2438.93,1281.07) v1@2447.46,1272.54 ; v1(2451,1269) 2355,1269 2335.68,1249.69
  Bottom Layer w10: v1@1559.46,1866.46 cw(c1550.93,1857.93) 1563,1857.93 cw(c1575.07,1857.93) v1@1566.54,1866.46 ; v1@1563,1875 ccw(c1563,1887.07) 1571.54,1878.54 ccw(c1580.07,1870) v1@1568,1870 ; v1@1594.46,2242.46 cw(c1585.93,2233.93) 1598,2233.93 cw(c1610.07,2233.93) v1@1601.54,2242.46 ; v1(1598,2246) 1598,1905 v1(1563,1870) 1563,1405 1817.5,1150.5 1817.5,648.5 v1(1853,613) ; v1@1848,613 ccw(c1835.93,613) 1844.46,621.54 ccw(c1853,630.07) v1@1853,618 ; v1@2099.11,616.54 ccw(c2090.57,625.07) 2102.64,625.07 ccw(c2114.72,625.07) v1@2106.18,616.54 ; v1(2102.64,613) 2102.64,1009.64 2122,1029 2122,1196 2202.37,1276.37 v1(2309,1276.37) ; v1@2305.46,1272.83 ccw(c2296.93,1264.3) 2296.93,1276.37 ccw(c2296.93,1288.44) v1@2305.46,1279.91 ; v1@2451,1264 cw(c2451,1251.93) 2459.54,1260.46 cw(c2468.07,1269) v1@2456,1269 ; v1(2451,1269) 2490.34,1229.66 2490.34,732.19 2607,615.53 2607,474 2700,381 2700,277.18 ; CN1.31@2649.61,226.79 2700,277.18 ; CN1.31@2650.57,248.18 ccw(c2652.57,292.53) 2683.96,261.14 ccw(c2715.35,229.75) CN1.31@2671,227.75 ; CN1.31@2651.02,258.17 ccw(c2653.95,323.22) 2700,277.18 ; CN1.31@2680.99,228.2 cw(c2746.04,231.14) 2700,277.18
PC14: CN1.35 R17.1 | length 1314.1
  Top Layer w10: R17.1@2098.16,757.16 cw(c2076.82,735.82) 2107,735.82 cw(c2137.18,735.82) R17.1@2115.84,757.16 ; R17.1@2107,766 2107,693 2214,586 2628,586 2800,414 2800,276.39 ; CN1.35@2818.24,228.57 ccw(c2755.73,232.12) 2800,276.39 ; CN1.35@2828.22,228 ccw(c2785.61,230.42) 2815.79,260.6 ccw(c2845.97,290.78) CN1.35@2848.39,248.17 ; CN1.35@2847.82,258.15 cw(c2844.27,320.66) 2800,276.39 ; CN1.35@2849.61,226.79 2800,276.39
PC15: CN1.33 R16.1 | length 1172.5
  Top Layer w10: R16.1@2290.77,757.16 cw(c2269.43,735.82) 2299.61,735.82 cw(c2329.79,735.82) R16.1@2308.45,757.16 ; R16.1@2299.61,765 2299.61,724.66 2338.27,686 v1(2387,686) ; v1@2383.46,682.46 ccw(c2374.93,673.93) 2374.93,686 ccw(c2374.93,698.07) v1@2383.46,689.54 ; v1(2432,505) 2434,507 2637,507 2700,444 2700,276.39 ; v1@2435.54,501.46 cw(c2448.9,488.1) 2448.9,507 ; CN1.33@2718.24,228.57 ccw(c2655.73,232.12) 2700,276.39 ; CN1.33@2728.22,228 ccw(c2685.61,230.42) 2715.79,260.6 ccw(c2745.97,290.78) CN1.33@2748.39,248.17 ; CN1.33@2747.82,258.15 cw(c2744.27,320.66) 2700,276.39 ; CN1.33@2749.61,226.79 2700,276.39
  Bottom Layer w10: v1@2387,681 cw(c2387,668.93) 2395.54,677.46 cw(c2404.07,686) v1@2392,686 ; v1(2387,686) 2432,641 v1(2432,505) ; v1@2428.46,508.54 ccw(c2419.93,517.07) 2432,517.07 ccw(c2444.07,517.07) v1@2435.54,508.54
PD0: C17.1 CN1.21 U1.48 | length 3694.4
  Top Layer w10: v1(2071,2152) 2554,2152 2647,2059 2647,2001.18 C17.1@2605.61,1959.79 2605.61,1930.06 ; v1@2074.54,2148.46 cw(c2083.07,2139.93) 2083.07,2152 cw(c2083.07,2164.07) v1@2074.54,2155.54 ; U1.48@2473.48,1733.38 2473.48,1797.94 2605.61,1930.06 ; C17.1@2596.86,1950.85 cw(c2576.51,1930.06) 2605.61,1930.06 ; C17.1@2605.61,1972.29 ccw(c2605.61,2002.47) 2626.95,1981.13 ccw(c2648.28,1959.79) C17.1@2618.11,1959.79 ; C17.1@2614.35,1950.85 ccw(c2634.7,1930.06) 2605.61,1930.06
  Bottom Layer w10: v1@2066,2152 cw(c2053.93,2152) 2062.46,2143.46 cw(c2071,2134.93) v1@2071,2147 ; v1(2071,2152) 2002,2083 2002,1753 1958,1709 1958,1482 1899,1423 1899,176 1937,138 2060.82,138 CN1.21@2149.61,226.79 ; CN1.21@2118.19,226.79 cw(c2042.34,226.79) 2095.97,173.16 cw(c2149.61,119.52) CN1.21@2149.61,195.37 ; CN1.21@2128.19,226.79 cw(c2076.48,226.79) 2113.04,190.23 cw(c2149.61,153.66) CN1.21@2149.61,205.37
PD1: C17.2 CN1.19 U1.49 | length 3273.9
  Top Layer w10: v1(2095,2127) 2536,2127 2605.61,2057.39 C17.2@2605.61,2019.79 2571.09,2019.79 2562.61,2011.31 2562.61,1923.61 2453.79,1814.8 U1.49@2453.79,1733.38 ; v1@2098.54,2123.46 cw(c2107.07,2114.93) 2107.07,2127 cw(c2107.07,2139.07) v1@2098.54,2130.54 ; C17.2@2596.77,2010.95 ccw(c2575.43,1989.61) 2575.43,2019.79 ccw(c2575.43,2049.97) 2596.77,2028.63 ccw(c2575.43,2049.97) 2605.61,2049.97 ccw(c2635.78,2049.97) C17.2@2614.45,2028.63
  Bottom Layer w10: CN1.19@2018.22,228.11 ccw(c1952.48,230.87) 1999,277.39 ; CN1.19@2028.21,227.69 ccw(c1983.39,229.57) 2015.11,261.28 ccw(c2046.83,293) CN1.19@2048.71,248.19 ; CN1.19@2048.29,258.18 cw(c2045.53,323.92) 1999,277.39 ; CN1.19@2049.61,226.79 1999,277.39 ; v1@2090,2127 cw(c2077.93,2127) 2086.46,2118.46 cw(c2095,2109.93) v1@2095,2122 ; v1(2095,2127) 2024,2056 2024,1740 1979,1695 1979,1465 1938,1424 1938,431 1999,370 1999,277.39
PD2: CN1.10 U1.75 | length 1523.2
  Top Layer w10: v6(1549.61,825.31) 1606.28,881.98 2093.5,1369.2 U1.75@2148.68,1369.2
  Bottom Layer w10: CN1.10@1527.39,349 ccw(c1473.76,402.64) 1549.61,402.64 ccw(c1625.45,402.64) CN1.10@1571.82,349 ; CN1.10@1534.46,341.93 ccw(c1497.9,378.49) 1549.61,378.49 ccw(c1601.31,378.49) CN1.10@1564.75,341.93 ; CN1.10@1549.61,326.79 v6(1549.61,825.31)
PD3: CN1.23 U1.76 | length 1584.4
  Top Layer w10: U1.76@2148.68,1349.52 2206.52,1349.52 2214,1357 2351,1357 v1(2352,1356) ; 2337.51,1357 cw(c2337.51,1341.51) v1@2348.46,1352.46
  Bottom Layer w10: CN1.23@2249.61,227.95 CN1.23@2249.61,226.79 2299.61,276.79 2299.61,977.61 2353,1031 2353,1355 v1(2352,1356) ; CN1.23@2250.7,248.18 ccw(c2252.91,291.65) 2283.69,260.87 ccw(c2314.47,230.09) CN1.23@2271,227.88 ; CN1.23@2251.2,258.16 ccw(c2254.45,321.94) 2299.6,276.79 ccw(c2344.76,231.63) CN1.23@2280.98,228.39 ; v1@2348.46,1352.46 cw(c2337.51,1341.51) 2353,1341.51
PD4: CN1.25 U1.77 | length 1618.7
  Top Layer w10: U1.77@2148.68,1329.83 v1(2379.83,1329.83) ; v1@2376.3,1326.3 ccw(c2367.76,1317.76) 2367.76,1329.83 ccw(c2367.76,1341.91) v1@2376.3,1333.37
  Bottom Layer w10: CN1.25@2349.61,226.79 2399.02,276.2 ; CN1.25@2350.88,248.17 ccw(c2353.4,290.37) 2383.29,260.47 ccw(c2413.18,230.58) CN1.25@2370.99,228.06 ; CN1.25@2351.48,258.15 ccw(c2355.17,320.05) 2399.02,276.2 ; v1@2376.3,1326.3 cw(c2367.76,1317.76) 2379.83,1317.76 cw(c2391.91,1317.76) v1@2383.37,1326.3 ; v1(2379.83,1329.83) 2379.83,1025.62 2329.27,975.06 2329.27,441.73 2399.02,371.98 2399.02,276.2 ; CN1.25@2380.97,228.66 cw(c2442.87,232.35) 2399.02,276.2
PD5: CN1.34 U1.78 | length 1848.2
  Top Layer w10: U1.78@2148.68,1310.15 2348.85,1310.15 2362,1297 v1(2412,1297) ; v1(2397.34,528) 2650.82,528 2749.61,429.22 CN1.34@2749.61,326.79 ; v1@2400.88,524.46 cw(c2409.42,515.93) 2409.42,528 cw(c2409.42,540.07) v1@2400.88,531.54 ; v1@2408.46,1293.46 ccw(c2399.93,1284.93) 2399.93,1297 ccw(c2399.93,1309.07) v1@2408.46,1300.54 ; CN1.34@2727.39,349 ccw(c2673.76,402.64) 2749.61,402.64 ccw(c2825.45,402.64) CN1.34@2771.82,349 ; CN1.34@2734.46,341.93 ccw(c2697.9,378.49) 2749.61,378.49 ccw(c2801.31,378.49) CN1.34@2764.75,341.93
  Bottom Layer w10: v1@2393.81,531.54 ccw(c2385.27,540.07) 2397.34,540.07 ccw(c2409.42,540.07) v1@2400.88,531.54 ; v1(2397.34,528) 2397.34,597.66 2358,637 2358,977.79 2412,1031.79 v1(2412,1297) ; v1@2408.46,1293.46 cw(c2399.93,1284.93) 2412,1284.93 cw(c2424.07,1284.93) v1@2415.54,1293.46
PD6: CN1.5 U1.1 | length 1787.5
  Top Layer w10: CN1.5@1318.24,228.66 ccw(c1256.34,232.35) 1300.19,276.2 ; CN1.5@1328.23,228.06 ccw(c1286.03,230.58) 1315.92,260.47 ccw(c1345.81,290.37) CN1.5@1348.33,248.17 ; CN1.5@1347.73,258.15 cw(c1344.04,320.05) 1300.19,276.2 ; CN1.5@1349.61,226.79 1300.19,276.2 ; U1.1@2237.26,1148.78 U1.1@2237.26,1182.2 ; U1.1@2237.26,1198.93 U1.1@2237.26,1182.2 ; 1300.19,276.2 1300.19,410.19 1459.2,569.2 1618.73,569.2 1635.2,569.2 1699.02,633.02 1699.02,804.48 2076.74,1182.2 U1.1@2237.26,1182.2
PD7: CN1.6 U1.2 | length 1798.6
  Top Layer w10: CN1.6@1349.61,326.79 CN1.6@1349.61,350.85 ; v1(1349.61,511.31) 1436.49,598.19 1620.19,598.19 1674,652 1674,807 2076.31,1209.31 2189.35,1209.31 2221.35,1241.31 2243.42,1241.31 2256.61,1228.13 2256.61,1182.54 U1.2@2256.94,1182.2 ; v1@1349.61,516.31 ccw(c1349.61,528.38) 1358.14,519.84 ccw(c1366.68,511.31) v1@1354.61,511.31
  Bottom Layer w10: CN1.6@1327.39,349 ccw(c1273.76,402.64) 1349.61,402.64 ccw(c1425.45,402.64) CN1.6@1371.82,349 ; CN1.6@1334.46,341.93 ccw(c1297.9,378.49) 1349.61,378.49 ccw(c1401.31,378.49) CN1.6@1364.75,341.93 ; v1@1346.07,507.77 cw(c1337.54,499.24) 1349.61,499.24 cw(c1361.68,499.24) v1@1353.14,507.77 ; CN1.6@1349.61,326.79 v1(1349.61,511.31)
PD8: CN1.7 U1.3 | length 1761.6
  Top Layer w10: CN1.7@1418.22,228.12 ccw(c1352.56,230.9) 1399.03,277.37 ; CN1.7@1428.21,227.69 ccw(c1383.45,229.59) 1415.13,261.27 ccw(c1446.81,292.95) CN1.7@1448.7,248.19 ; CN1.7@1448.28,258.18 cw(c1445.5,323.84) 1399.03,277.37 ; CN1.7@1449.61,226.79 1399.02,277.37 ; U1.3@2276.63,1182.2 2276.63,1134.42 2261.51,1119.31 2261.44,1119.38 2039.38,1119.38 1723,803 1723,606.55 1641.45,525 1456.08,525 1399.02,467.94 1399.02,277.37
PD9: CN1.8 U1.4 | length 1620.8
  Top Layer w10: CN1.8@1427.39,349 ccw(c1380.05,396.34) 1447,396.34 ; CN1.8@1434.46,341.93 ccw(c1404.19,372.2) 1447,372.2 ; 1447,384.79 ccw(c1507.6,384.79) CN1.8@1464.75,341.93 ; 1447,408.93 ccw(c1531.75,408.93) CN1.8@1471.82,349 ; CN1.8@1449.61,326.79 1447,329.39 1447,439 1502,494 1647,494 1757,604 1757,805 2051.31,1099.31 2256.06,1099.31 2256.13,1099.24 2268.24,1099.24 2268.31,1099.31 2296.31,1127.31 U1.4@2296.31,1182.2
PD10: CN2.5 U1.34 | length 2926.4
  Top Layer w10: CN2.5@1327.39,2584.57 cw(c1273.76,2530.94) 1349.61,2530.94 cw(c1425.45,2530.94) CN2.5@1371.82,2584.57 ; CN2.5@1334.46,2591.64 cw(c1297.9,2555.08) 1349.61,2555.08 cw(c1401.31,2555.08) CN2.5@1364.75,2591.64 ; CN2.5@1349.61,2606.79 1349.61,2426.39 1422.09,2353.91 2770.28,2353.91 2913,2211.19 2913,2004 2958,1959 2958,1643 2841.68,1526.69 U1.34@2699.86,1526.69
PD11: CN2.6 U1.35 | length 2989.4
  Top Layer w10: CN2.6@1318.22,2705.35 cw(c1253.32,2702.38) 1299.26,2656.44 ; CN2.6@1328.21,2705.81 cw(c1283.97,2703.78) 1315.29,2672.47 cw(c1346.6,2641.15) CN2.6@1348.63,2685.39 ; CN2.6@1348.17,2675.4 ccw(c1345.2,2610.5) 1299.26,2656.44 ; CN2.6@1349.61,2706.79 1299.26,2656.44 ; U1.35@2699.86,1546.37 2700.24,1545.98 2815.99,1545.98 2931.19,1661.19 2931.19,1951.81 2891,1992 2891,2197 2767.69,2320.31 1425.69,2320.31 1299.26,2446.74 1299.26,2656.44
PD12: CN2.7 U1.36 | length 3051.3
  Top Layer w10: CN2.7@1427.39,2584.57 cw(c1373.76,2530.94) 1449.61,2530.94 cw(c1525.45,2530.94) CN2.7@1471.82,2584.57 ; CN2.7@1434.46,2591.64 cw(c1397.9,2555.08) 1449.61,2555.08 cw(c1501.31,2555.08) CN2.7@1464.75,2591.64 ; CN2.7@1449.61,2606.79 1449.61,2435.39 1476.69,2408.31 2816.69,2408.31 2957,2268 2957,2063 3046,1974 v1(3046,1772) ; U1.36@2699.86,1566.06 2799.05,1566.06 2883,1650 v1(2883,1771) ; v1@2879.46,1767.46 cw(c2870.93,1758.93) 2883,1758.93 cw(c2895.07,1758.93) v1@2886.54,1767.46 ; v1@3042.46,1775.54 ccw(c3033.93,1784.07) 3046,1784.07 ccw(c3058.07,1784.07) v1@3049.54,1775.54
  Bottom Layer w10: v1(2883,1771) v1@3045,1771 ; v1@2886.54,1767.46 cw(c2895.07,1758.93) 2895.07,1771 cw(c2895.07,1783.07) v1@2886.54,1774.54 ; 3031.52,1771 ccw(c3031.52,1786.49) v1@3042.46,1775.54
PD13: CN2.8 U1.37 | length 3117.5
  Top Layer w10: 1416.1,2672.12 ccw(c1386.44,2701.78) CN2.8@1428.26,2705.1 ; 1416.93,2672.94 cw(c1447.05,2642.81) CN2.8@1448.75,2685.39 ; CN2.8@1418.29,2704.3 cw(c1358.03,2699.53) 1400.77,2656.79 cw(c1445.82,2611.75) CN2.8@1448.35,2675.4 ; CN2.8@1449.61,2706.79 1449.61,2705.62 1400.19,2656.2 1400.19,2432.81 1451.69,2381.31 2796.78,2381.31 2936,2242.09 2936,2030 3001,1965 v1(3001,1732) ; U1.37@2699.86,1585.74 2787.74,1585.74 2836,1634 v1(2836,1732) ; v1@2832.46,1728.46 cw(c2823.93,1719.93) 2836,1719.93 cw(c2848.07,1719.93) v1@2839.54,1728.46 ; v1@2997.46,1735.54 ccw(c2988.93,1744.07) 3001,1744.07 ccw(c3013.07,1744.07) v1@3004.54,1735.54
  Bottom Layer w10: v1(2836,1732) v1(3001,1732) ; v1@2839.54,1728.46 cw(c2848.07,1719.93) 2848.07,1732 cw(c2848.07,1744.07) v1@2839.54,1735.54 ; v1@2997.46,1728.46 ccw(c2988.93,1719.93) 2988.93,1732 ccw(c2988.93,1744.07) v1@2997.46,1735.54
PD14: CN2.3 U1.56 | length 1988.4
  Top Layer w10: v1(1397,1911.49) 2210.88,1911.49 2316,1806.37 U1.56@2316,1733.38 ; v1@1400.54,1907.95 cw(c1409.07,1899.42) 1409.07,1911.49 cw(c1409.07,1923.56) v1@1400.54,1915.02
  Bottom Layer w10: CN2.3@1249.61,2606.79 1296,2560.39 ; CN2.3@1251.91,2585.5 cw(c1255.78,2549.72) 1281.23,2575.16 cw(c1306.68,2600.61) CN2.3@1270.9,2604.48 ; CN2.3@1252.99,2575.55 cw(c1258.67,2523.07) 1296,2560.4 ; CN2.3@1280.84,2603.41 ccw(c1333.33,2597.73) 1296,2560.4 ; v1@1392,1911.49 ccw(c1379.93,1911.49) 1388.46,1920.02 ccw(c1397,1928.56) v1@1397,1916.49 ; v1(1397,1911.49) 1296,2012.49 1296,2560.39
PD15: CN2.4 U1.57 | length 2262.6
  Top Layer w10: v1(1311,1830) 1557,1830 1606,1879 2217.91,1879 2296.31,1800.6 U1.57@2296.31,1733.38 ; v1@1314.54,1826.46 cw(c1323.07,1817.93) 1323.07,1830 cw(c1323.07,1842.07) v1@1314.54,1833.54
  Bottom Layer w10: CN2.4@1218.24,2704.92 cw(c1156.34,2701.22) 1200.19,2657.37 ; CN2.4@1228.23,2705.51 cw(c1186.03,2702.99) 1215.92,2673.1 cw(c1245.81,2643.21) CN2.4@1248.33,2685.41 ; CN2.4@1247.74,2675.43 ccw(c1244.04,2613.52) 1200.19,2657.37 ; CN2.4@1249.61,2706.79 1200.19,2657.37 ; v1@1306,1830 ccw(c1293.93,1830) 1302.46,1838.54 ccw(c1311,1847.07) v1@1311,1835 ; v1(1311,1830) 1261,1880 1261,2455 1200.19,2515.81 1200.19,2657.37
PE0: CN2.1 U1.58 | length 2188.3
  Top Layer w10: v1(1292,1805) 1574,1805 1621,1852 2219.46,1852 2276.63,1794.83 U1.58@2276.63,1733.38 ; v1@1295.54,1801.46 cw(c1304.07,1792.93) 1304.07,1805 cw(c1304.07,1817.07) v1@1295.54,1808.54
  Bottom Layer w10: CN2.1@1127.39,2584.57 cw(c1073.76,2530.94) 1149.61,2530.94 cw(c1225.45,2530.94) CN2.1@1171.82,2584.57 ; CN2.1@1134.46,2591.64 cw(c1097.9,2555.08) 1149.61,2555.08 cw(c1201.31,2555.08) CN2.1@1164.75,2591.64 ; CN2.1@1149.61,2606.79 1149.61,2490.39 1232,2408 1232,1865 v1(1292,1805) ; v1@1287,1805 ccw(c1274.93,1805) 1283.46,1813.54 ccw(c1292,1822.07) v1@1292,1810
PE1: CN2.2 U1.59 | length 2334
  Top Layer w10: v1(1274,1780) 1588,1780 1629,1821 2225,1821 2256.94,1789.06 U1.59@2256.94,1733.38 ; v1@1277.54,1776.46 cw(c1286.07,1767.93) 1286.07,1780 cw(c1286.07,1792.07) v1@1277.54,1783.54
  Bottom Layer w10: CN2.2@1118.19,2706.79 cw(c1042.34,2706.79) 1095.97,2653.16 cw(c1149.61,2599.52) CN2.2@1149.61,2675.37 ; CN2.2@1128.19,2706.79 cw(c1076.48,2706.79) 1113.04,2670.23 cw(c1149.61,2633.66) CN2.2@1149.61,2685.37 ; CN2.2@1149.61,2706.79 1090.94,2648.13 1090.94,2468.06 1194,2365 1194,1860 v1(1274,1780) ; v1@1269,1780 ccw(c1256.93,1780) 1265.46,1788.54 ccw(c1274,1797.07) v1@1274,1785
PE2: CN1.1 U1.73 | length 1864.2
  Top Layer w10: CN1.1@1118.24,228.62 ccw(c1056.08,232.25) 1100.11,276.29 ; CN1.1@1128.23,228.04 ccw(c1085.85,230.51) 1115.86,260.53 ccw(c1145.88,290.55) CN1.1@1148.36,248.17 ; CN1.1@1147.77,258.15 cw(c1144.14,320.32) 1100.11,276.29 ; CN1.1@1149.61,226.79 1100.11,276.29 ; U1.73@2148.68,1408.57 2061.87,1408.57 1586,932.7 1586,932.47 1100.11,446.58 1100.11,276.29
PE3: CN1.2 U1.74 | length 1717.9
  Top Layer w10: CN1.2@1127.39,349 ccw(c1073.76,402.64) 1149.61,402.64 ccw(c1225.45,402.64) CN1.2@1171.82,349 ; CN1.2@1134.46,341.93 ccw(c1097.9,378.49) 1149.61,378.49 ccw(c1201.31,378.49) CN1.2@1164.75,341.93 ; CN1.2@1149.61,326.79 1149.61,460.31 2078.57,1389.28 2148.29,1389.28 U1.74@2148.68,1388.89
PE4: CN1.3 U1.79 | length 1730.7
  Top Layer w10: CN1.3@1218.24,228.66 ccw(c1156.34,232.35) 1200.19,276.2 ; CN1.3@1228.23,228.06 ccw(c1186.03,230.58) 1215.92,260.47 ccw(c1245.81,290.37) CN1.3@1248.33,248.17 ; CN1.3@1247.73,258.15 cw(c1244.04,320.05) 1200.19,276.2 ; CN1.3@1249.61,226.79 1200.19,276.2 ; U1.79@2148.68,1290.46 2056.76,1290.46 1587.09,820.79 1555.3,789 1515,789 1200.19,474.19 1200.19,276.2
PE5: CN1.4 U1.80 | length 1588.2
  Top Layer w10: CN1.4@1227.39,349 ccw(c1173.76,402.64) 1249.61,402.64 ccw(c1325.45,402.64) CN1.4@1271.82,349 ; CN1.4@1234.46,341.93 ccw(c1197.9,378.49) 1249.61,378.49 ccw(c1301.31,378.49) CN1.4@1264.75,341.93 ; CN1.4@1249.61,326.79 1249.61,493.61 1527,771 1562.76,771 2062.54,1270.78 U1.80@2148.68,1270.78
PF0: CN1.39 R19.2 | length 1010.8
  Top Layer w10: R19.2@2789.77,814.47 cw(c2768.43,793.13) 2798.61,793.13 cw(c2828.78,793.13) R19.2@2807.45,814.47 ; R19.2@2798.61,823.31 2798.61,708.39 2871,636 v1(2974,636) ; v1@2970.46,632.46 ccw(c2961.93,623.93) 2961.93,636 ccw(c2961.93,648.07) v1@2970.46,639.54
  Bottom Layer w10: v1@2970.46,632.46 cw(c2961.93,623.93) 2974,623.93 cw(c2986.07,623.93) v1@2977.54,632.46 ; v1(2974,636) 2974,533 3002.19,504.81 3002.19,274.21 ; CN1.39@3018.32,229.64 ccw(c2962.7,234.71) 3002.19,274.2 ; CN1.39@3028.28,228.73 ccw(c2990.36,232.19) 3017.28,259.11 ccw(c3044.21,286.03) CN1.39@3047.66,248.12 ; CN1.39@3046.75,258.08 cw(c3041.68,313.7) 3002.19,274.2 ; CN1.39@3049.61,226.79 3002.19,274.21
